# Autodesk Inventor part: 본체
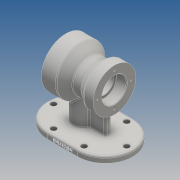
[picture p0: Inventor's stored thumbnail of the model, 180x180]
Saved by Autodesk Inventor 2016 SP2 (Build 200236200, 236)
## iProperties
Created: 2020-01
Part Number: 본체
Material: 알루미늄 6061
Document SubType Name: Modeling
Designer: EZ
Density: 2.7 g/cm^3
Appearance: 기본값
Mass: 930.253 g
Surface Area: 651.434 cm^2
Volume: 344.538 cm^3
Author: EZ
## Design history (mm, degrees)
sketch "스케치1"
  geometry: L1 (0, 0)-(-80, 0); L2 (0, 40)-(0, 26); L3 (0, 26)-(-19.7, 26); L4 (-20, 25.7)-(-20, 16); L5 (-20, 16)-(-63, 16); L6 (-63, 16)-(-63, 19.7); L7 (-63.3, 20)-(-80, 20); L8 (-80, 20)-(-80, 35); L9 (-80, 35)-(-64, 35); L10 (-64, 35)-(-53.289, 27.5); L11 (-53.289, 27.5)-(-38.897, 27.5); L12 (-38.897, 27.5)-(-24, 40); L13 (-24, 40)-(0, 40); A1 r 0.3 centre (-19.7, 25.7) between (-19.7, 26) and (-20, 25.7); A2 r 0.3 centre (-63.3, 19.7) between (-63, 19.7) and (-63.3, 20)
  constraints: 27 end point, 7 perpendicular, 4 point on circle, 4 tangent, 2 centre point, 2 parallel, 2 point on line, 1 equal radius, 1 horizontal, 1 vertical
  dimensions: "d0" = 80 distance of L1.start L1.end; "d2" = 80 diameter of L13 L1; "d3" = 52 diameter of L3 L1; "d4" = 20 distance between parallel lines of L4 L2; "d5" = 17 distance between parallel lines of L8 L6; "d6" = 24 distance of L12.end L2.start; "d7" = 16 distance of L8.end L9.end; "d8" = 32 diameter of L5 L1; "d9" = 40 diameter of L7 L1; "d10" = 70 diameter of L9 L1; "d11" = 55 diameter of L11 L1; "d12" = 0.3 radius of A1; "d13" = 40 deg angle of L12 L11; "d14" = 35 deg angle of L10 L11
revolve "회전1" sketch "스케치1" stored, may be unused: angle "d15" = 90 deg
fillet "모깎기1" dims "d16" = 3
chamfer "모따기1" distance "d17" = 1; stored, may be unused: second distance "d18" = 2, angle "d19" = 45 deg
node "작업 평면1"
sketch "스케치2"
  geometry: L1 (15, 0)-(65, 0); L2 (15, -45)-(65, -45); L3 (65, 45)-(15, 45); L4 (0, 40)-(0, -40) reference; L5 (0, 0)-(145.446, 0); A1 r 45 centre (15, 0) between (15, 45) and (15, -45); A2 r 45 centre (65, 0) between (65, -45) and (65, 45); 1 further point
  constraints: 10 end point, 4 point on circle, 4 tangent, 2 centre point, 2 horizontal, 1 midpoint, 1 parallel, 1 other
  dimensions: "d21" = 50 distance of L1.start L1.end; "d23" = 45 radius of A1; "d25" = 30 distance edge to line of A1 L4
extrude "돌출1" join sketch "스케치2" distance "d26" = 10; taper "d27" = 0 deg
sketch "스케치3"
  geometry: L1 (65, 45)-(15, 45) reference; L2 (15, -45)-(65, -45) reference; L3 (65, 45)-(15, 45) reference; L4 (65, -35)-(15, -35); L5 (15, 35)-(65, 35); A1 r 45 centre (65, 0) between (65, -45) and (65, 45) reference; A2 r 45 centre (15, 0) between (15, 45) and (15, -45) reference; A3 r 45 centre (15, 0) between (15, 45) and (15, -45) reference; A4 r 45 centre (65, 0) between (65, -45) and (65, 45) reference; A5 r 35 centre (15, 0) between (15, 35) and (15, -35); A6 r 35 centre (65, 0) between (65, -35) and (65, 35); 6 further points
  constraints: 6 point on circle, 4 coincident, 4 end point, 2 centre point, 3 other
  dimensions: "d29" = 10 distance between parallel lines of L2 L4
hole "구멍1" sketch "스케치3" at (15, -35), (65, -35), (100, 0), (65, 35), (15, 35), (-20, 0) diameter "d30" = 9; stored, may be unused: countersink angle "d34" = 90 deg, drill point angle "d36" = 118 deg; dims "d31" = 6, "d32" = 4, "d33" = 2, "d35" = 8
sketch "스케치4"
  geometry: L1 (-30, 0)-(28, 0); L2 (43.199, 5)-(70, 5); L3 (70, 5)-(70, -5); L4 (70, -5)-(43.199, -5); L5 (80, 35)-(80, -35) reference; A1 r 45 centre (15, 0) between (15, 45) and (15, -45) reference; A2 r 16 centre (28, 0) between (43.199, 5) and (43.199, -5)
  constraints: 8 end point, 3 point on circle, 2 horizontal, 2 perpendicular, 1 centre point, 1 coincident, 1 other
  dimensions: "d38" = 58 distance of L1.start L1.end; "d39" = 32 diameter of A2; "d41" = 10 distance of L2.end L3.end; "d77" = 10 distance between parallel lines of L5 L3
extrude "돌출2" join sketch "스케치4" stored distance "d42" = 10; taper "d43" = 0 deg
fillet "모깎기4" dims "d46" = 3
sketch "스케치5" dims "d47" = 66
  geometry: 3 further points
  constraints: 2 horizontal alignment, 1 coincident, 2 other
hole "구멍2" sketch "스케치5" at (33, 0) diameter "d48" = 3.242; stored, may be unused: countersink angle "d52" = 90 deg, drill point angle "d54" = 118 deg; dims "d49" = 9, "d50" = 4, "d51" = 2, "d53" = 11
sketch "스케치6" dims "d58" = 55
  geometry: 3 further points
  constraints: 2 horizontal alignment, 1 coincident, 2 other
hole "구멍3" sketch "스케치6" at (-27.5, 0) diameter "d59" = 3.242; stored, may be unused: countersink angle "d63" = 90 deg, drill point angle "d65" = 118 deg; dims "d60" = 9, "d61" = 4, "d62" = 2, "d64" = 11
sketch "스케치7"
  geometry: L1 (95, 0)-(50, 0) reference; L2 (-45, 0)-(-45, 7) reference; 2 further points
  constraints: 1 other
  dimensions: "d69" = 4 distance from line of L1 point (25, 4); "d70" = 70 distance from line of L2 point (25, 4)
feature "엠보싱1" sketch "스케치7" dims "d71" = 0.5, "d72" = 0
fillet "모깎기6" dims "d74" = 3
fillet "모깎기7" dims "d75" = 3
fillet "모깎기8" dims "d76" = 3
fillet "모깎기9" dims "d78" = 3
node "솔리드1"
pattern_circular "원형 패턴1" dims angle "d56" = 360 deg
pattern_circular "원형 패턴2" dims angle "d67" = 360 deg
node "투영된 루프1"
